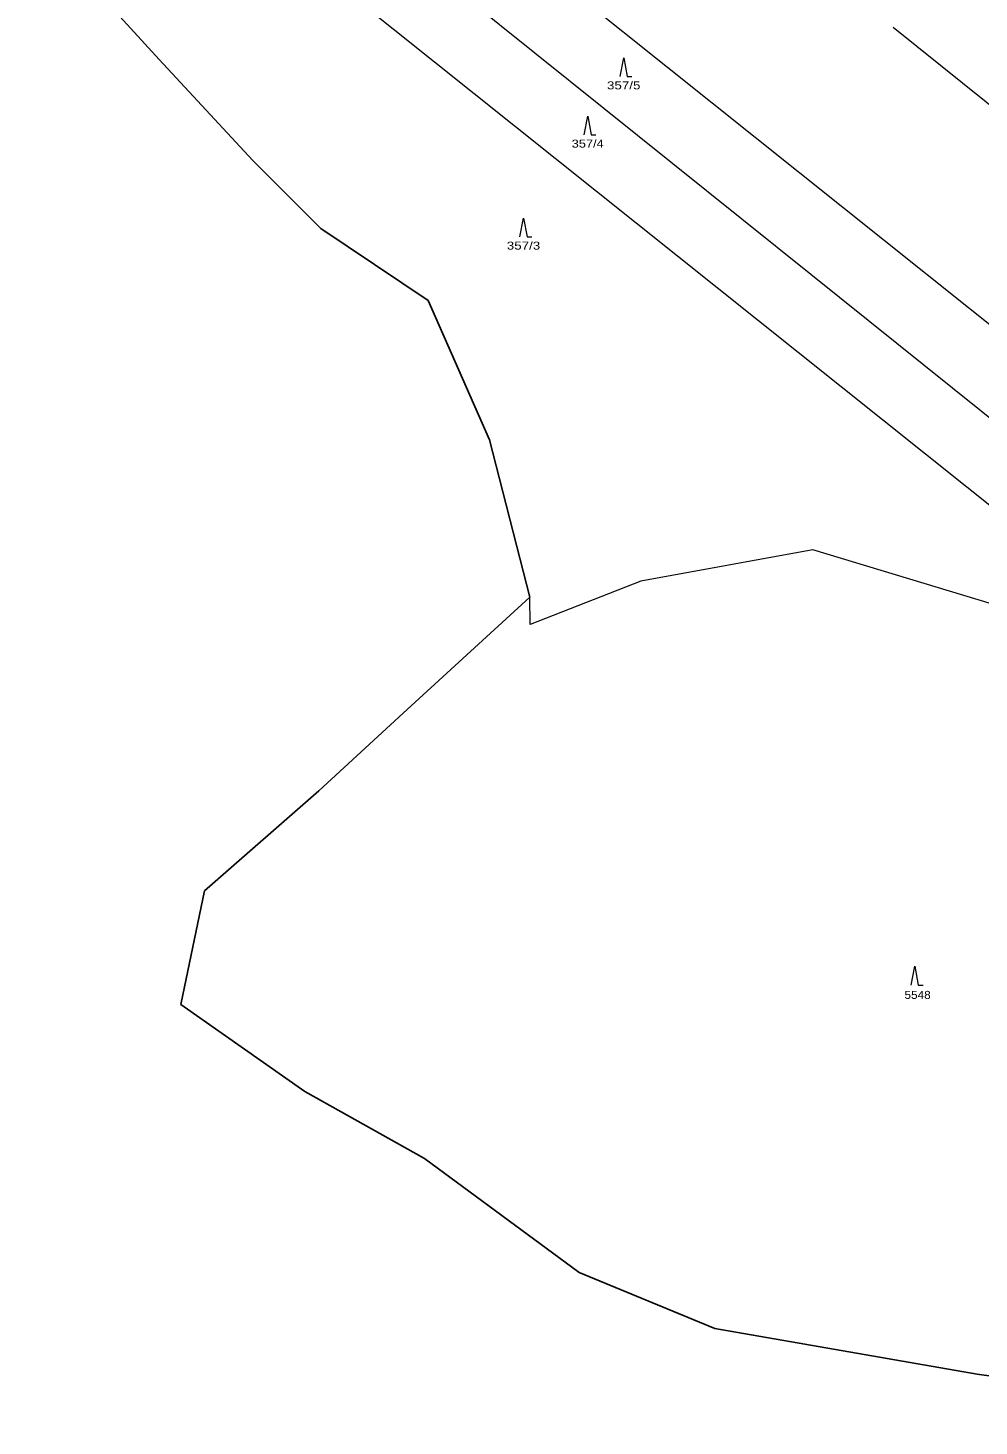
# Model space of a CAD drawing. Extents: x -590528 to -586543, y -1119609 to -1116685.
# Drawn here: x -590131.6 to -589929.4, y -1118500.5 to -1118203.4 of the extents above; entities that cross this region are included whole.
import ezdxf
from ezdxf.enums import TextEntityAlignment as Align

# ---------------------------------------------------------------- set-up
doc = ezdxf.new("R2010")
doc.units = 0
doc.header["$LTSCALE"] = 0.68
for name, color, linetype, lineweight in [('1', 7, 'Continuous', 13), ('3', 7, 'Continuous', 13), ('4', 7, 'Continuous', 25), ('6', 7, 'Continuous', 13)]:
    doc.layers.add(name, color=color, linetype=linetype, lineweight=lineweight)

msp = doc.modelspace()

# ---------------------------------------------------------------- linework, layer by layer
at = {"layer": '1'}
for p, q in [((-589958.41, -1118241.57), (-590119.15, -1118113.18)), ((-590125.28, -1118127.29), (-589965.19, -1118255.72)), ((-589967.89, -1118272.4), (-590131.61, -1118141.69)), ((-589947.68, -1118203.28), (-589781.66, -1118336.64)), ((-589801.18, -1118367.15), (-589958.41, -1118241.57)), ((-589965.19, -1118255.72), (-589806.56, -1118382.97)), ((-589809.28, -1118399.02), (-589967.89, -1118272.4))]:
    msp.add_line(p, q, dxfattribs=at)
for points in [[(-589912.04, -1118330.23), (-589964.79, -1118314.31), (-590001.3, -1118320.96)], [(-590001.3, -1118320.96), (-590024.86, -1118330.14), (-590024.89, -1118324.37)]]:
    msp.add_lwpolyline(points, dxfattribs=at)
at = {"layer": '4'}
for p, q in [((-590120.32, -1118191.94), (-590103.73, -1118210.15)), ((-590083.82, -1118231.57), (-590103.73, -1118210.15)), ((-590083.82, -1118231.57), (-590069.38, -1118246.03)), ((-590046.55, -1118261.33), (-590069.38, -1118246.03)), ((-590046.55, -1118261.33), (-590033.51, -1118290.94)), ((-590024.89, -1118324.37), (-590033.51, -1118290.94)), ((-590040.03, -1118338.16), (-590024.89, -1118324.37)), ((-590099.1, -1118410.88), (-590094.08, -1118386.74)), ((-590099.1, -1118410.88), (-590072.77, -1118429.37)), ((-590014.43, -1118467.84), (-589985.59, -1118479.77)), ((-589985.59, -1118479.77), (-589929.84, -1118489.42)), ((-589929.84, -1118489.42), (-589851.47, -1118500.47))]:
    msp.add_line(p, q, dxfattribs=at)
for points in [[(-590040.03, -1118338.16), (-590051.87, -1118349.03), (-590069.76, -1118365.53), (-590094.08, -1118386.74)], [(-590072.77, -1118429.37), (-590047.34, -1118443.63), (-590014.43, -1118467.84)]]:
    msp.add_lwpolyline(points, dxfattribs=at)
at = {"layer": '6'}
for points in [[(-590005.71, -1118213.77), (-590004.96, -1118209.77), (-590004.21, -1118213.77), (-590003.21, -1118213.77)], [(-590013.36, -1118226.15), (-590012.61, -1118222.15), (-590011.86, -1118226.15), (-590010.86, -1118226.15)], [(-590027.01, -1118247.82), (-590026.26, -1118243.82), (-590025.51, -1118247.82), (-590024.51, -1118247.82)], [(-589943.83, -1118406.77), (-589943.08, -1118402.77), (-589942.33, -1118406.77), (-589941.33, -1118406.77)]]:
    msp.add_lwpolyline(points, dxfattribs=at)

# ---------------------------------------------------------------- texts
at = {"layer": '3'}
for s, width, p in [('357/5', 1.25, (-590004.9605, -1118216.47)), ('357/4', 1.2, (-590012.6105, -1118228.85)), ('357/3', 1.25, (-590026.2605, -1118250.52))]:
    msp.add_text(s, height=1.7, dxfattribs=dict(at, width=width)).set_placement(p, align=Align.CENTER)
at = {"layer": '3', "width": 1.1}
msp.add_text('5548', height=1.7, dxfattribs=at).set_placement((-589945.263, -1118409.72))

doc.saveas('drawing.dxf')
